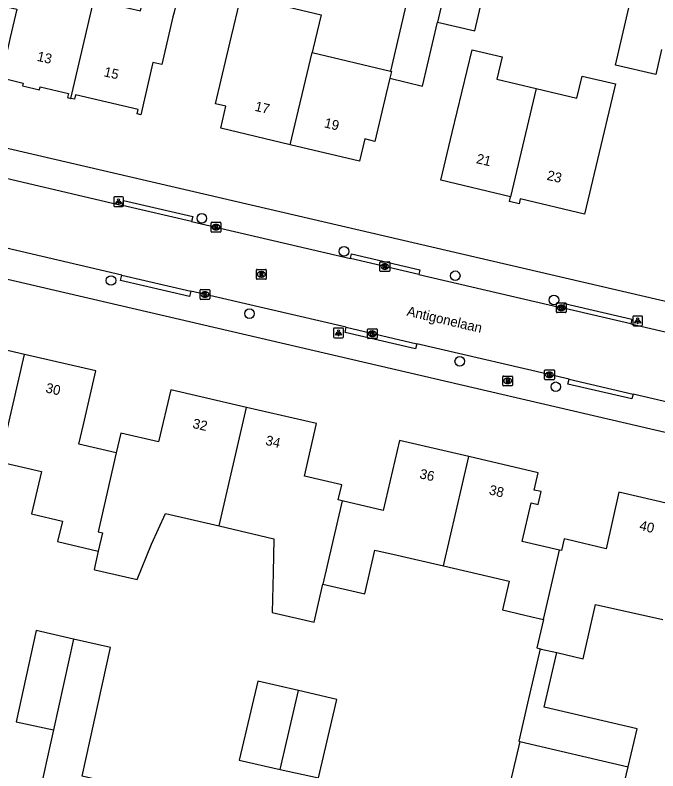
# Model space of a CAD drawing. Extents: x 162186 to 163152, y 385513 to 386513.
# Drawn here: x 162587.4 to 162652.9, y 385877.9 to 385954.9 of the extents above; entities that cross this region are included whole.
import ezdxf

# ---------------------------------------------------------------- set-up
doc = ezdxf.new("R2010")
doc.units = 0
for name, color, linetype in [('IMGEO_Boom', 7, 'Continuous'), ('IMGEO_Brandkraan', 7, 'Continuous'), ('IMGEO_Erf', 7, 'Continuous'), ('IMGEO_Kolk', 7, 'Continuous'), ('IMGEO_Lichtpunt', 7, 'Continuous'), ('IMGEO_Openbare_ruimte_label', 7, 'Continuous'), ('IMGEO_Pand', 7, 'Continuous'), ('IMGEO_Pand_nummerreeks', 7, 'Continuous'), ('IMGEO_Rijbaan_lokaal_open', 7, 'Continuous'), ('IMGEO_Rioolput', 7, 'Continuous'), ('IMGEO_Voetpad_open', 7, 'Continuous')]:
    doc.layers.add(name, color=color, linetype=linetype)

msp = doc.modelspace()

# ---------------------------------------------------------------- linework, layer by layer
at = {"layer": 'IMGEO_Boom'}
for centre in [(162606.436, 385934.207), (162620.933, 385930.85), (162632.267, 385928.363), (162597.18, 385927.876), (162642.328, 385925.887), (162611.297, 385924.503), (162632.729, 385919.642), (162642.52, 385917.05)]:
    msp.add_circle(centre, 0.489, dxfattribs=at)
at = {"layer": 'IMGEO_Brandkraan'}
for p, q in [((162637.108, 385917.221), (162637.108, 385918.073)), ((162637.183, 385918.147), (162638.035, 385918.147)), ((162637.596, 385917.927), (162637.621, 385917.927)), ((162638.109, 385918.073), (162638.109, 385917.221)), ((162638.035, 385917.147), (162637.183, 385917.147)), ((162637.619, 385917.367), (162637.594, 385917.367))]:
    msp.add_line(p, q, dxfattribs=at)
for points in [[(162637.108, 385917.221), (162637.108, 385918.073)], [(162637.183, 385918.147), (162638.035, 385918.147)], [(162637.456, 385917.847), (162637.456, 385917.447), (162637.669, 385917.447)], [(162637.687, 385917.847), (162637.456, 385917.847)], [(162638.109, 385918.073), (162638.109, 385917.221)], [(162638.035, 385917.147), (162637.183, 385917.147)], [(162637.635, 385917.766), (162637.581, 385917.766), (162637.581, 385917.69)], [(162637.581, 385917.69), (162637.634, 385917.69)], [(162637.643, 385917.614), (162637.581, 385917.614), (162637.581, 385917.533)], [(162637.581, 385917.533), (162637.643, 385917.533)]]:
    msp.add_lwpolyline(points, dxfattribs=at)
for centre, radius, start, end in [((162637.185, 385918.071), 0.0765, 91.55205, 178.44795), ((162637.185, 385918.071), 0.0765, 91.55205, 178.44795), ((162637.691, 385917.702), 0.145, 59.4692, 91.53667), ((162637.716, 385917.749), 0.0922, 285.51372, 58.15012), ((162638.033, 385918.071), 0.0765, 1.55205, 88.44795), ((162638.033, 385918.071), 0.0765, 1.55205, 88.44795), ((162637.185, 385917.223), 0.0765, 181.55205, 268.44795), ((162637.185, 385917.223), 0.0765, 181.55205, 268.44795), ((162637.636, 385917.728), 0.0379, 267.82845, 90.93552), ((162637.644, 385917.573), 0.0404, 269.87594, 90.50774), ((162637.675, 385917.698), 0.251, 268.66757, 293.53466), ((162637.721, 385917.557), 0.105, 301.31148, 78.98903), ((162638.033, 385917.223), 0.0765, 271.55205, 358.44795), ((162638.033, 385917.223), 0.0765, 271.55205, 358.44795)]:
    msp.add_arc(centre, radius, start, end, dxfattribs=at)
for centre, major_axis, ratio, start_param, end_param in [((162637.595, 385917.647), (-0.387, 0.002), 0.722429, 4.712389, 7.853982), ((162637.62, 385917.647), (-0.39, 0.002), 0.717154, 1.570796, 4.712389)]:
    msp.add_ellipse(centre, major_axis=major_axis, ratio=ratio, start_param=start_param, end_param=end_param, dxfattribs=at)
at = {"layer": 'IMGEO_Erf'}
for points in [[(162629.646, 385965.47), (162629.445, 385965.517), (162627.833, 385958.556), (162625.653, 385949.215)], [(162625.597, 385948.48), (162628.926, 385947.687), (162630.448, 385954.213)]]:
    msp.add_lwpolyline(points, dxfattribs=at)
at = {"layer": 'IMGEO_Kolk'}
for p, q in [((162607.378, 385932.881), (162607.378, 385933.733)), ((162607.453, 385933.807), (162608.305, 385933.807)), ((162607.866, 385933.587), (162607.891, 385933.587)), ((162608.379, 385933.733), (162608.379, 385932.881)), ((162608.305, 385932.807), (162607.453, 385932.807)), ((162607.889, 385933.027), (162607.864, 385933.027)), ((162624.59, 385928.869), (162624.59, 385929.721)), ((162624.665, 385929.795), (162625.517, 385929.795)), ((162625.078, 385929.575), (162625.103, 385929.575)), ((162625.591, 385929.721), (162625.591, 385928.869)), ((162625.517, 385928.795), (162624.665, 385928.795)), ((162625.101, 385929.015), (162625.076, 385929.015)), ((162606.25, 385926.03), (162606.25, 385926.882)), ((162606.325, 385926.956), (162607.177, 385926.956)), ((162606.738, 385926.736), (162606.763, 385926.736)), ((162607.251, 385926.882), (162607.251, 385926.03)), ((162607.177, 385925.956), (162606.325, 385925.956)), ((162606.761, 385926.176), (162606.736, 385926.176)), ((162642.58, 385924.676), (162642.58, 385925.528)), ((162642.655, 385925.602), (162643.507, 385925.602)), ((162643.581, 385925.528), (162643.581, 385924.676)), ((162643.091, 385924.822), (162643.066, 385924.822)), ((162643.068, 385925.382), (162643.093, 385925.382)), ((162643.507, 385924.602), (162642.655, 385924.602)), ((162623.322, 385922.03), (162623.322, 385922.882)), ((162623.397, 385922.956), (162624.249, 385922.956)), ((162623.81, 385922.736), (162623.835, 385922.736)), ((162624.323, 385922.882), (162624.323, 385922.03)), ((162624.249, 385921.956), (162623.397, 385921.956)), ((162623.833, 385922.176), (162623.808, 385922.176)), ((162641.374, 385917.846), (162641.374, 385918.698)), ((162641.449, 385918.772), (162642.301, 385918.772)), ((162642.375, 385918.698), (162642.375, 385917.846)), ((162641.885, 385917.992), (162641.86, 385917.992)), ((162641.862, 385918.552), (162641.887, 385918.552)), ((162642.301, 385917.772), (162641.449, 385917.772))]:
    msp.add_line(p, q, dxfattribs=at)
for points in [[(162607.378, 385932.881), (162607.378, 385933.733)], [(162607.453, 385933.807), (162608.305, 385933.807)], [(162607.699, 385933.507), (162607.822, 385933.507), (162607.822, 385933.356), (162607.952, 385933.507), (162608.116, 385933.507), (162607.97, 385933.356), (162608.123, 385933.107), (162607.971, 385933.107), (162607.886, 385933.271), (162607.822, 385933.204), (162607.822, 385933.107), (162607.699, 385933.107), (162607.699, 385933.507)], [(162608.379, 385933.733), (162608.379, 385932.881)], [(162608.305, 385932.807), (162607.453, 385932.807)], [(162624.59, 385928.869), (162624.59, 385929.721)], [(162624.665, 385929.795), (162625.517, 385929.795)], [(162624.911, 385929.495), (162625.034, 385929.495), (162625.034, 385929.344), (162625.164, 385929.495), (162625.328, 385929.495), (162625.182, 385929.344), (162625.335, 385929.095), (162625.183, 385929.095), (162625.098, 385929.259), (162625.034, 385929.192), (162625.034, 385929.095), (162624.911, 385929.095), (162624.911, 385929.495)], [(162625.591, 385929.721), (162625.591, 385928.869)], [(162625.517, 385928.795), (162624.665, 385928.795)], [(162606.25, 385926.03), (162606.25, 385926.882)], [(162606.325, 385926.956), (162607.177, 385926.956)], [(162606.571, 385926.656), (162606.694, 385926.656), (162606.694, 385926.505), (162606.824, 385926.656), (162606.988, 385926.656), (162606.842, 385926.505), (162606.995, 385926.256), (162606.843, 385926.256), (162606.758, 385926.42), (162606.694, 385926.353), (162606.694, 385926.256), (162606.571, 385926.256), (162606.571, 385926.656)], [(162607.251, 385926.882), (162607.251, 385926.03)], [(162607.177, 385925.956), (162606.325, 385925.956)], [(162642.58, 385924.676), (162642.58, 385925.528)], [(162642.655, 385925.602), (162643.507, 385925.602)], [(162643.581, 385925.528), (162643.581, 385924.676)], [(162642.901, 385925.302), (162643.024, 385925.302), (162643.024, 385925.151), (162643.154, 385925.302), (162643.318, 385925.302), (162643.172, 385925.151), (162643.325, 385924.902), (162643.173, 385924.902), (162643.088, 385925.066), (162643.024, 385924.999), (162643.024, 385924.902), (162642.901, 385924.902), (162642.901, 385925.302)], [(162643.507, 385924.602), (162642.655, 385924.602)], [(162623.322, 385922.03), (162623.322, 385922.882)], [(162623.397, 385922.956), (162624.249, 385922.956)], [(162623.643, 385922.656), (162623.766, 385922.656), (162623.766, 385922.505), (162623.896, 385922.656), (162624.06, 385922.656), (162623.914, 385922.505), (162624.067, 385922.256), (162623.915, 385922.256), (162623.83, 385922.42), (162623.766, 385922.353), (162623.766, 385922.256), (162623.643, 385922.256), (162623.643, 385922.656)], [(162624.323, 385922.882), (162624.323, 385922.03)], [(162624.249, 385921.956), (162623.397, 385921.956)], [(162641.374, 385917.846), (162641.374, 385918.698)], [(162641.449, 385918.772), (162642.301, 385918.772)], [(162642.375, 385918.698), (162642.375, 385917.846)], [(162641.695, 385918.472), (162641.818, 385918.472), (162641.818, 385918.321), (162641.948, 385918.472), (162642.112, 385918.472), (162641.966, 385918.321), (162642.119, 385918.072), (162641.967, 385918.072), (162641.882, 385918.236), (162641.818, 385918.169), (162641.818, 385918.072), (162641.695, 385918.072), (162641.695, 385918.472)], [(162642.301, 385917.772), (162641.449, 385917.772)]]:
    msp.add_lwpolyline(points, dxfattribs=at)
for centre, start, end in [((162607.455, 385933.731), 91.55205, 178.44795), ((162607.455, 385933.731), 91.55205, 178.44795), ((162608.303, 385933.731), 1.55205, 88.44795), ((162608.303, 385933.731), 1.55205, 88.44795), ((162607.455, 385932.883), 181.55205, 268.44795), ((162607.455, 385932.883), 181.55205, 268.44795), ((162608.303, 385932.883), 271.55205, 358.44795), ((162608.303, 385932.883), 271.55205, 358.44795), ((162624.667, 385929.719), 91.55205, 178.44795), ((162624.667, 385929.719), 91.55205, 178.44795), ((162625.515, 385929.719), 1.55205, 88.44795), ((162625.515, 385929.719), 1.55205, 88.44795), ((162624.667, 385928.871), 181.55205, 268.44795), ((162624.667, 385928.871), 181.55205, 268.44795), ((162625.515, 385928.871), 271.55205, 358.44795), ((162625.515, 385928.871), 271.55205, 358.44795), ((162606.327, 385926.88), 91.55205, 178.44795), ((162606.327, 385926.88), 91.55205, 178.44795), ((162607.175, 385926.88), 1.55205, 88.44795), ((162607.175, 385926.88), 1.55205, 88.44795), ((162606.327, 385926.032), 181.55205, 268.44795), ((162606.327, 385926.032), 181.55205, 268.44795), ((162607.175, 385926.032), 271.55205, 358.44795), ((162607.175, 385926.032), 271.55205, 358.44795), ((162642.657, 385925.526), 91.55205, 178.44795), ((162642.657, 385925.526), 91.55205, 178.44795), ((162643.505, 385925.526), 1.55205, 88.44795), ((162643.505, 385925.526), 1.55205, 88.44795), ((162642.657, 385924.678), 181.55205, 268.44795), ((162642.657, 385924.678), 181.55205, 268.44795), ((162643.505, 385924.678), 271.55205, 358.44795), ((162643.505, 385924.678), 271.55205, 358.44795), ((162623.399, 385922.88), 91.55205, 178.44795), ((162623.399, 385922.88), 91.55205, 178.44795), ((162624.247, 385922.88), 1.55205, 88.44795), ((162624.247, 385922.88), 1.55205, 88.44795), ((162623.399, 385922.032), 181.55205, 268.44795), ((162623.399, 385922.032), 181.55205, 268.44795), ((162624.247, 385922.032), 271.55205, 358.44795), ((162624.247, 385922.032), 271.55205, 358.44795), ((162641.451, 385918.696), 91.55205, 178.44795), ((162641.451, 385918.696), 91.55205, 178.44795), ((162642.299, 385918.696), 1.55205, 88.44795), ((162642.299, 385918.696), 1.55205, 88.44795), ((162641.451, 385917.848), 181.55205, 268.44795), ((162641.451, 385917.848), 181.55205, 268.44795), ((162642.299, 385917.848), 271.55205, 358.44795), ((162642.299, 385917.848), 271.55205, 358.44795)]:
    msp.add_arc(centre, 0.0765, start, end, dxfattribs=at)
for centre, major_axis, ratio, start_param, end_param in [((162607.865, 385933.307), (-0.387, 0.002), 0.722429, 4.712389, 7.853982), ((162607.89, 385933.307), (-0.39, 0.002), 0.717154, 1.570796, 4.712389), ((162625.077, 385929.295), (-0.387, 0.002), 0.722429, 4.712389, 7.853982), ((162625.102, 385929.295), (-0.39, 0.002), 0.717154, 1.570796, 4.712389), ((162606.737, 385926.456), (-0.387, 0.002), 0.722429, 4.712389, 7.853982), ((162606.762, 385926.456), (-0.39, 0.002), 0.717154, 1.570796, 4.712389), ((162643.067, 385925.102), (-0.387, 0.002), 0.722429, 4.712389, 7.853982), ((162643.092, 385925.102), (-0.39, 0.002), 0.717154, 1.570796, 4.712389), ((162623.809, 385922.456), (-0.387, 0.002), 0.722429, 4.712389, 7.853982), ((162623.834, 385922.456), (-0.39, 0.002), 0.717154, 1.570796, 4.712389), ((162641.861, 385918.272), (-0.387, 0.002), 0.722429, 4.712389, 7.853982), ((162641.886, 385918.272), (-0.39, 0.002), 0.717154, 1.570796, 4.712389)]:
    msp.add_ellipse(centre, major_axis=major_axis, ratio=ratio, start_param=start_param, end_param=end_param, dxfattribs=at)
at = {"layer": 'IMGEO_Lichtpunt'}
for p, q in [((162597.452, 385936.314), (162597.452, 385935.507)), ((162597.452, 385936.314), (162597.452, 385935.507)), ((162598.354, 385936.409), (162597.546, 385936.409)), ((162598.354, 385936.409), (162597.546, 385936.409)), ((162598.448, 385935.507), (162598.448, 385936.314)), ((162598.448, 385935.507), (162598.448, 385936.314)), ((162597.546, 385935.413), (162598.354, 385935.413)), ((162597.546, 385935.413), (162598.354, 385935.413)), ((162650.366, 385924.162), (162650.366, 385923.355)), ((162650.366, 385924.162), (162650.366, 385923.355)), ((162651.268, 385924.257), (162650.46, 385924.257)), ((162651.268, 385924.257), (162650.46, 385924.257)), ((162651.362, 385923.355), (162651.362, 385924.162)), ((162651.362, 385923.355), (162651.362, 385924.162)), ((162650.46, 385923.261), (162651.268, 385923.261)), ((162650.46, 385923.261), (162651.268, 385923.261)), ((162619.873, 385922.941), (162619.873, 385922.134)), ((162619.873, 385922.941), (162619.873, 385922.134)), ((162620.775, 385923.036), (162619.967, 385923.036)), ((162620.775, 385923.036), (162619.967, 385923.036)), ((162620.869, 385922.134), (162620.869, 385922.941)), ((162620.869, 385922.134), (162620.869, 385922.941)), ((162619.967, 385922.04), (162620.775, 385922.04)), ((162619.967, 385922.04), (162620.775, 385922.04))]:
    msp.add_line(p, q, dxfattribs=at)
for points in [[(162597.826, 385935.978), (162597.865, 385935.95), (162597.677, 385935.688), (162597.639, 385935.715), (162597.826, 385935.978)], [(162597.928, 385935.93), (162597.975, 385935.93), (162597.975, 385935.608), (162597.928, 385935.608), (162597.928, 385935.93)], [(162598.038, 385935.95), (162598.076, 385935.977), (162598.263, 385935.715), (162598.224, 385935.687), (162598.038, 385935.95)], [(162650.74, 385923.826), (162650.779, 385923.798), (162650.591, 385923.536), (162650.553, 385923.563), (162650.74, 385923.826)], [(162650.842, 385923.778), (162650.889, 385923.778), (162650.889, 385923.456), (162650.842, 385923.456), (162650.842, 385923.778)], [(162650.952, 385923.798), (162650.99, 385923.825), (162651.177, 385923.563), (162651.138, 385923.535), (162650.952, 385923.798)], [(162620.247, 385922.605), (162620.286, 385922.577), (162620.098, 385922.315), (162620.06, 385922.342), (162620.247, 385922.605)], [(162620.349, 385922.557), (162620.396, 385922.557), (162620.396, 385922.235), (162620.349, 385922.235), (162620.349, 385922.557)], [(162620.459, 385922.577), (162620.497, 385922.604), (162620.684, 385922.342), (162620.645, 385922.314), (162620.459, 385922.577)]]:
    msp.add_lwpolyline(points, dxfattribs=at)
for centre in [(162597.951, 385936.112), (162650.865, 385923.96), (162620.372, 385922.739)]:
    msp.add_circle(centre, 0.0994, dxfattribs=at)
for centre, start, end in [((162597.546, 385936.314), 90, 180), ((162597.546, 385936.314), 90, 180), ((162598.354, 385936.314), 0, 90), ((162598.354, 385936.314), 0, 90), ((162597.546, 385935.507), 180, 270), ((162597.546, 385935.507), 180, 270), ((162598.354, 385935.507), 270, 0), ((162598.354, 385935.507), 270, 360), ((162650.46, 385924.162), 90, 180), ((162650.46, 385924.162), 90, 180), ((162651.268, 385924.162), 0, 90), ((162651.268, 385924.162), 0, 90), ((162650.46, 385923.355), 180, 270), ((162650.46, 385923.355), 180, 270), ((162651.268, 385923.355), 270, 0), ((162651.268, 385923.355), 270, 360), ((162619.967, 385922.941), 90, 180), ((162619.967, 385922.941), 90, 180), ((162620.775, 385922.941), 0, 90), ((162620.775, 385922.941), 0, 90), ((162619.967, 385922.134), 180, 270), ((162619.967, 385922.134), 180, 270), ((162620.775, 385922.134), 270, 0), ((162620.775, 385922.134), 270, 360)]:
    msp.add_arc(centre, 0.0946, start, end, dxfattribs=at)
at = {"layer": 'IMGEO_Pand'}
for points in [[(162630.448, 385954.213), (162634.274, 385953.326), (162636.708, 385963.834), (162632.896, 385964.717)], [(162653.306, 385951.425), (162652.706, 385948.878), (162648.607, 385949.827), (162651.08, 385960.505), (162655.219, 385959.546)], [(162595.438, 385956.466), (162600.184, 385955.356), (162601.103, 385959.288), (162604.377, 385958.522), (162603.602, 385955.211), (162603.492, 385954.743), (162602.353, 385949.874), (162601.447, 385950.085), (162600.203, 385944.768), (162599.846, 385944.851), (162599.947, 385945.286), (162593.546, 385946.783), (162593.443, 385946.341), (162593.085, 385946.425)], [(162631.269, 385957.737), (162630.448, 385954.213)], [(162583.726, 385956.412), (162587.567, 385955.514), (162586.895, 385952.64), (162585.83, 385948.086), (162586.206, 385947.998), (162586.311, 385948.444), (162588.221, 385947.998), (162588.151, 385947.699), (162589.877, 385947.295), (162589.953, 385947.62), (162592.828, 385946.948), (162592.726, 385946.509), (162593.085, 385946.425)], [(162593.085, 385946.425), (162595.438, 385956.466)], [(162615.44, 385941.718), (162608.362, 385943.404), (162608.894, 385945.636), (162607.824, 385945.892), (162608.983, 385950.756), (162609.465, 385952.777), (162609.699, 385953.758), (162610.448, 385956.905), (162618.597, 385954.963), (162617.78, 385951.537), (162617.679, 385951.114)], [(162615.44, 385941.718), (162617.679, 385951.114)], [(162617.679, 385951.114), (162625.653, 385949.215)], [(162637.902, 385936.403), (162630.812, 385938.094), (162631.972, 385942.958), (162633.983, 385951.389), (162637.038, 385950.66), (162636.498, 385948.396), (162640.529, 385947.435)], [(162625.653, 385949.215), (162625.766, 385949.188), (162625.597, 385948.48)], [(162640.529, 385947.435), (162644.671, 385946.442), (162645.212, 385948.71), (162648.592, 385947.904), (162646.589, 385939.51), (162645.429, 385934.646), (162638.891, 385936.206), (162638.77, 385935.701), (162637.79, 385935.934), (162637.902, 385936.403)], [(162625.597, 385948.48), (162625.226, 385946.922), (162624.067, 385942.058), (162623.062, 385942.297), (162622.522, 385940.031), (162615.44, 385941.718)], [(162640.529, 385947.435), (162637.902, 385936.403)], [(162588.352, 385920.347), (162581.077, 385922.034), (162579.991, 385917.352), (162579.353, 385914.602), (162575.527, 385915.489)], [(162585.815, 385909.407), (162588.352, 385920.347)], [(162597.703, 385910.33), (162593.904, 385911.211), (162594.365, 385913.198), (162595.631, 385918.659), (162588.352, 385920.347)], [(162610.999, 385914.944), (162603.263, 385916.738), (162602.032, 385911.431), (162598.166, 385912.328), (162597.703, 385910.33)], [(162608.202, 385902.866), (162610.999, 385914.944)], [(162620.737, 385905.424), (162620.344, 385905.515), (162620.703, 385907.064), (162616.887, 385907.949), (162618.126, 385913.292), (162610.999, 385914.944)], [(162633.653, 385909.93), (162626.577, 385911.571), (162624.926, 385904.453), (162620.737, 385905.424)], [(162597.703, 385910.33), (162595.852, 385902.273), (162596.311, 385902.167), (162595.881, 385900.312)], [(162585.815, 385909.407), (162590.077, 385908.419), (162589.074, 385904.093), (162592.221, 385903.363), (162591.736, 385901.273), (162595.881, 385900.312)], [(162631.071, 385898.789), (162633.653, 385909.93)], [(162642.899, 385900.417), (162639.093, 385901.299), (162640, 385905.208), (162640.72, 385905.041), (162641.027, 385906.365), (162640.321, 385906.529), (162640.729, 385908.289), (162633.653, 385909.93)], [(162656.108, 385904.635), (162648.96, 385906.32), (162647.671, 385900.547), (162643.682, 385901.471), (162643.387, 385901.539), (162643.115, 385900.367), (162642.899, 385900.417)], [(162620.737, 385905.424), (162618.781, 385896.952)], [(162595.881, 385900.312), (162595.444, 385898.427), (162595.523, 385898.408), (162599.852, 385897.405), (162601.32, 385901.006), (162602.741, 385904.132), (162608.202, 385902.866)], [(162608.202, 385902.866), (162613.787, 385901.571), (162613.697, 385898.13), (162613.59, 385894.041), (162617.88, 385893.051), (162618.781, 385896.952)], [(162618.781, 385896.952), (162623.047, 385895.963), (162624.078, 385900.411), (162626.359, 385899.882), (162631.071, 385898.789)], [(162641.257, 385893.337), (162642.899, 385900.417)], [(162631.071, 385898.789), (162635.601, 385897.739), (162637.783, 385897.233), (162637.082, 385894.305), (162640.064, 385893.614), (162641.257, 385893.337)], [(162642.617, 385889.963), (162645.293, 385889.343), (162646.576, 385894.876), (162653.442, 385893.324)], [(162641.257, 385893.337), (162640.584, 385890.435), (162640.931, 385890.354)], [(162593.339, 385891.346), (162589.536, 385892.216), (162587.493, 385882.919), (162591.303, 385882.082)], [(162593.339, 385891.346), (162591.303, 385882.082)], [(162601.597, 385873.01), (162597.157, 385874.04), (162597.742, 385876.562), (162594.248, 385877.372), (162597.13, 385890.478), (162593.339, 385891.346)], [(162640.931, 385890.354), (162639.646, 385884.81), (162638.747, 385880.935), (162638.858, 385880.909)], [(162640.931, 385890.354), (162641.045, 385890.328), (162642.617, 385889.963)], [(162649.904, 385878.319), (162650.818, 385882.191), (162641.331, 385884.415), (162642.617, 385889.963)], [(162616.274, 385886.095), (162612.138, 385887.042), (162611.434, 385884.036), (162610.257, 385879.01), (162614.414, 385878.036)], [(162614.414, 385878.036), (162616.274, 385886.095)], [(162614.414, 385878.036), (162618.328, 385877.188), (162620.204, 385885.196), (162616.274, 385886.095)], [(162591.303, 385882.082), (162589.723, 385874.89), (162593.519, 385874.056), (162593.692, 385874.844), (162594.416, 385874.676), (162593.403, 385870.308), (162592.332, 385870.557), (162591.792, 385868.229), (162592.863, 385867.98), (162591.868, 385863.693), (162598.548, 385862.143), (162598.436, 385861.66), (162598.942, 385861.543)], [(162638.858, 385880.909), (162637.027, 385873.14), (162640.961, 385872.21), (162641.619, 385874.994), (162648.723, 385873.317), (162649.904, 385878.319)], [(162638.858, 385880.909), (162649.904, 385878.319)]]:
    msp.add_lwpolyline(points, dxfattribs=at)
at = {"layer": 'IMGEO_Rijbaan_lokaal_open'}
for points in [[(162582.997, 385939.105), (162598.335, 385935.527)], [(162605.387, 385933.891), (162598.335, 385935.527)], [(162605.387, 385933.891), (162621.586, 385930.116)], [(162598.285, 385928.43), (162583.586, 385931.839)], [(162628.553, 385928.5), (162621.586, 385930.116)], [(162598.285, 385928.43), (162605.316, 385926.792)], [(162628.553, 385928.5), (162643.294, 385925.05)], [(162621.165, 385923.11), (162605.316, 385926.792)], [(162650.169, 385923.455), (162643.294, 385925.05)], [(162650.169, 385923.455), (162666.053, 385919.762)], [(162621.165, 385923.11), (162628.35, 385921.436)], [(162643.88, 385917.817), (162628.35, 385921.436)], [(162643.88, 385917.817), (162650.397, 385916.299)], [(162666.138, 385912.642), (162650.397, 385916.299)]]:
    msp.add_lwpolyline(points, dxfattribs=at)
at = {"layer": 'IMGEO_Rioolput'}
for p, q in [((162612, 385928.08), (162612, 385928.932)), ((162612.075, 385929.006), (162612.927, 385929.006)), ((162612.488, 385928.786), (162612.513, 385928.786)), ((162613.001, 385928.932), (162613.001, 385928.08)), ((162612.927, 385928.006), (162612.075, 385928.006)), ((162612.511, 385928.226), (162612.486, 385928.226))]:
    msp.add_line(p, q, dxfattribs=at)
for points in [[(162612, 385928.08), (162612, 385928.932)], [(162612.075, 385929.006), (162612.927, 385929.006)], [(162612.589, 385928.704), (162612.337, 385928.706), (162612.337, 385928.306)], [(162612.515, 385928.625), (162612.461, 385928.625), (162612.461, 385928.544)], [(162613.001, 385928.932), (162613.001, 385928.08)], [(162612.927, 385928.006), (162612.075, 385928.006)], [(162612.337, 385928.306), (162612.461, 385928.306), (162612.461, 385928.468), (162612.472, 385928.468)], [(162612.461, 385928.544), (162612.513, 385928.544)], [(162612.519, 385928.439), (162612.59, 385928.306), (162612.73, 385928.306), (162612.665, 385928.432)]]:
    msp.add_lwpolyline(points, dxfattribs=at)
for centre, radius, start, end in [((162612.077, 385928.93), 0.0765, 91.55205, 178.44795), ((162612.077, 385928.93), 0.0765, 91.55205, 178.44795), ((162612.521, 385928.529), 0.0964, 77.00612, 93.18647), ((162612.535, 385928.586), 0.0378, 276.66336, 79.67722), ((162612.588, 385928.594), 0.109, 350.36119, 89.41601), ((162612.925, 385928.93), 0.0765, 1.55205, 88.44795), ((162612.925, 385928.93), 0.0765, 1.55205, 88.44795), ((162612.077, 385928.082), 0.0765, 181.55205, 268.44795), ((162612.077, 385928.082), 0.0765, 181.55205, 268.44795), ((162612.471, 385928.415), 0.0533, 26.02933, 88.69889), ((162612.497, 385928.733), 0.19, 274.7715, 282.96867), ((162612.586, 385928.594), 0.112, 277.58423, 350.98172), ((162612.57, 385928.379), 0.108, 29.51342, 73.79051), ((162612.925, 385928.082), 0.0765, 271.55205, 358.44795), ((162612.925, 385928.082), 0.0765, 271.55205, 358.44795)]:
    msp.add_arc(centre, radius, start, end, dxfattribs=at)
for centre, major_axis, ratio, start_param, end_param in [((162612.487, 385928.506), (-0.387, 0.002), 0.722429, 4.712389, 7.853982), ((162612.512, 385928.506), (-0.39, 0.002), 0.717154, 1.570796, 4.712389)]:
    msp.add_ellipse(centre, major_axis=major_axis, ratio=ratio, start_param=start_param, end_param=end_param, dxfattribs=at)
at = {"layer": 'IMGEO_Voetpad_open'}
for points in [[(162750.77, 385903.177), (162747.115, 385904.027), (162535.867, 385953.127)], [(162532.931, 385940.487), (162533.141, 385940.448), (162742.31, 385891.809)], [(162598.335, 385935.527), (162598.451, 385936.013), (162605.505, 385934.384), (162605.387, 385933.891)], [(162621.586, 385930.116), (162621.703, 385930.595), (162628.668, 385928.973), (162628.553, 385928.5)], [(162605.316, 385926.792), (162605.186, 385926.256), (162598.155, 385927.891), (162598.285, 385928.43)], [(162643.294, 385925.05), (162643.405, 385925.531), (162650.281, 385923.942), (162650.169, 385923.455)], [(162628.35, 385921.436), (162628.227, 385920.924), (162621.04, 385922.59), (162621.165, 385923.11)], [(162650.397, 385916.299), (162650.28, 385915.814), (162643.761, 385917.324), (162643.88, 385917.817)]]:
    msp.add_lwpolyline(points, dxfattribs=at)

# ---------------------------------------------------------------- texts
at = {"layer": 'IMGEO_Openbare_ruimte_label'}
msp.add_text('Antigonelaan', height=1, rotation=346.88086, dxfattribs=at).set_placement((162627.27, 385924.306))
at = {"layer": 'IMGEO_Pand_nummerreeks'}
for s, rotation, p in [('13', 346.95948, (162589.572, 385950.276)), ('15', 346.95948, (162596.39, 385948.697)), ('17', 346.60425, (162611.771, 385945.183)), ('19', 346.60425, (162618.851, 385943.496)), ('21', 346.72457, (162634.35, 385939.85)), ('23', 346.72457, (162641.549, 385938.151)), ('30', 346.94416, (162590.449, 385916.494)), ('32', 346.94802, (162605.43, 385912.868)), ('34', 346.94802, (162612.864, 385911.144)), ('36', 346.94229, (162628.569, 385907.741)), ('38', 346.94229, (162635.648, 385906.1)), ('40', 346.73603, (162650.979, 385902.475))]:
    msp.add_text(s, height=1, rotation=rotation, dxfattribs=at).set_placement(p)

doc.saveas('drawing.dxf')
